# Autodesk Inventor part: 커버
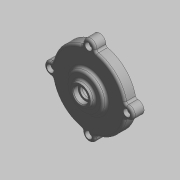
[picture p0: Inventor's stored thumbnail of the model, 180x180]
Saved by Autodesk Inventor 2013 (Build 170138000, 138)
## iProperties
Created: 2015-11
Part Number: 커버
Document SubType Name: 모델링
Designer: mdu
Material: 알루미늄 6061
Density: 2.71 g/cm^3
Mass: 196.657 g
Surface Area: 278.607 cm^2
Volume: 72.5671 cm^3
변환 표준: STEP AP214IS
파일 이름: C:\Users\SeoGD\Desktop\?쒗뿕\而ㅻ쾭-1.stp
전처리기: Build: 253, Release: 2010 SP1 - Date: Wed 07/29/2009
전송 단위: 밀리미터
불확실성: 0.01
Author: mdu
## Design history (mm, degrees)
sketch "스케치1"
  geometry: L1 (0, 0)-(0, 26); L2 (50, 0)-(50, 15); L3 (50, 15)-(25, 15); L4 (25, 15)-(25, 21); L5 (25, 21)-(15, 21); L6 (15, 21)-(13.66, 26); L7 (13.66, 26)-(10, 26); L8 (50, 0)-(45, 0); L9 (45, 0)-(45, 10); L10 (45, 10)-(14.5, 10); L11 (14.5, 10)-(13.266, 3); L12 (13.266, 3)-(11, 3); L13 (11, 3)-(11, 16); L14 (11, 16)-(7.5, 16); L15 (7.5, 16)-(7.5, 19); L16 (7.5, 19)-(10, 19); L17 (10, 19)-(10, 26)
  constraints: 34 end point, 10 parallel, 2 perpendicular, 2 point on line, 1 vertical
  dimensions: "d11" = 100 diameter of L2 L1; "d12" = 22 diameter of L13 L1; "d13" = 90 diameter of L9 L1; "d14" = 15 distance between parallel lines of L3 L8; "d15" = 10 distance between parallel lines of L8 L10; "d16" = 29 diameter of L10.end L1; "d17" = 100 deg angle of L11 L10; "d18" = 7 distance between parallel lines of L12 L10; "d19" = 13 distance between parallel lines of L14 L12; "d20" = 3 distance between parallel lines of L16 L14; "d21" = 15 diameter of L15 L1; "d22" = 20 diameter of L17 L1; "d23" = 30 diameter of L5.end L1; "d24" = 6 distance between parallel lines of L5 L3; "d25" = 50 diameter of L4 L1; "d26" = 105 deg angle of L5 L6; "d50" = 26 distance of L1.start L1.end
revolve "회전1" sketch "스케치1" stored, may be unused: angle "d27" = 90 deg
sketch "스케치2" dims "d29" = 104
  geometry: A1 r 8.5 centre (0, 52) between (8.074, 49.344) and (-8.074, 49.344); A2 r 50 centre (0, 0) between (-8.074, 49.344) and (8.074, 49.344) reference; 2 further points
  constraints: 4 point on circle, 2 vertical alignment, 1 centre point, 1 coincident, 2 other
  dimensions: "d28" = 17 diameter of A1
extrude "돌출1" join sketch "스케치2" stored distance "d30" = 10; taper "d31" = 0 deg
fillet "모깎기3" dims "d32" = 3
fillet "모깎기4" dims "d45" = 3, "d46" = 0.2
chamfer "모따기1" distance "d47" = 1; stored, may be unused: second distance "d48" = 2, angle "d49" = 45 deg
hole "구멍2" diameter "d38" = 5.5; stored, may be unused: countersink angle "d42" = 90 deg, drill point angle "d44" = 118 deg; dims "d39" = 6, "d40" = 9.5, "d41" = 5.4, "d43" = 8, "d54" = 10, "d55" = 10
node "솔리드1"
node "솔리드 본체"
node "곡면 본체"
pattern_circular "원형 패턴1" dims angle "d34" = 360 deg
pattern_circular "원형 패턴2" dims angle "d52" = 360 deg
node "솔리드2"
